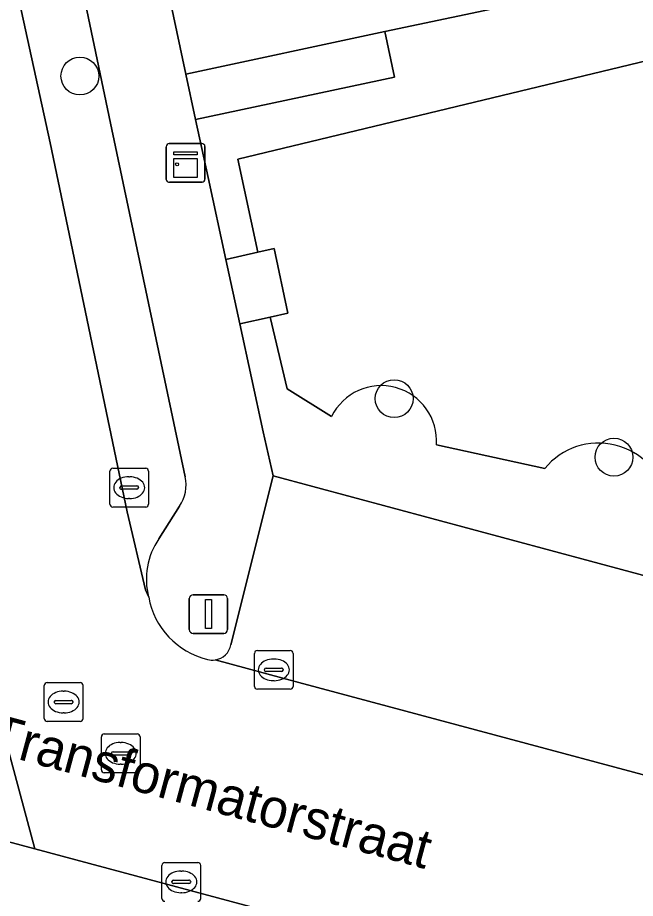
# Model space of a CAD drawing. Extents: x 162989 to 165008, y 383432 to 384338.
# Drawn here: x 163591.23 to 163607.2, y 383947.94 to 383970.69 of the extents above; entities that cross this region are included whole.
import ezdxf

# ---------------------------------------------------------------- set-up
doc = ezdxf.new("R2010")
doc.units = 0
for name, color, linetype in [('IMGEO_Boom', 7, 'Continuous'), ('IMGEO_Groenvoorziening', 7, 'Continuous'), ('IMGEO_Kast', 7, 'Continuous'), ('IMGEO_Kolk', 7, 'Continuous'), ('IMGEO_Lichtmast', 7, 'Continuous'), ('IMGEO_Openbare_ruimte_label', 7, 'Continuous'), ('IMGEO_Pand', 7, 'Continuous'), ('IMGEO_Parkeervlak_open', 7, 'Continuous'), ('IMGEO_Rijbaan_lokaal_open', 7, 'Continuous'), ('IMGEO_Rioolput', 7, 'Continuous'), ('IMGEO_Terreindeel_open', 7, 'Continuous'), ('IMGEO_Voetpad_open', 7, 'Continuous')]:
    doc.layers.add(name, color=color, linetype=linetype)

msp = doc.modelspace()

# ---------------------------------------------------------------- linework, layer by layer
at = {"layer": 'IMGEO_Boom'}
for centre in [(163592.845, 383969.176), (163600.967, 383960.844), (163606.648, 383959.331)]:
    msp.add_circle(centre, 0.489, dxfattribs=at)
at = {"layer": 'IMGEO_Groenvoorziening'}
for points in [[(163645.161, 383948.398), (163625.646, 383970.458), (163622.066, 383974.209), (163621.361, 383974.962), (163613.606, 383973.04), (163610.957, 383972.488), (163605.03, 383971.243), (163600.725, 383970.324), (163600.976, 383969.15), (163595.835, 383968.052), (163596.159, 383966.556), (163596.618, 383964.44), (163597.446, 383964.625), (163596.93, 383967.033), (163621.397, 383972.93), (163634.327, 383958.335), (163641.287, 383950.771), (163639.916, 383949.332), (163636.067, 383950.448)], [(163636.067, 383950.448), (163639.916, 383949.332), (163641.287, 383950.771), (163634.327, 383958.335), (163621.397, 383972.93), (163596.93, 383967.033), (163597.446, 383964.625), (163597.864, 383964.718), (163598.223, 383963.048), (163597.764, 383962.949), (163598.199, 383961.094), (163599.35, 383960.383)], [(163599.35, 383960.383), (163598.199, 383961.094), (163597.764, 383962.949), (163596.978, 383962.778), (163597.581, 383959.99), (163597.843, 383958.853), (163614.246, 383954.444), (163635.514, 383948.776), (163643.317, 383946.719), (163645.161, 383948.398)], [(163604.861, 383959.041), (163602.059, 383959.651)], [(163602.059, 383959.651), (163604.861, 383959.041)]]:
    msp.add_lwpolyline(points, dxfattribs=at)
for centre, radius, start, end in [((163600.632, 383959.749), 1.43, 356.062, 153.6963), ((163600.632, 383959.749), 1.43, 356.062, 153.6963), ((163606.248, 383957.904), 1.794, 11.5882, 140.6482), ((163606.248, 383957.904), 1.794, 11.5882, 140.6482)]:
    msp.add_arc(centre, radius, start, end, dxfattribs=at)
at = {"layer": 'IMGEO_Kast'}
for p, q in [((163595.078, 383966.507), (163595.078, 383967.348)), ((163595.078, 383967.348), (163595.078, 383966.507)), ((163595.153, 383967.432), (163595.994, 383967.432)), ((163595.994, 383967.432), (163595.153, 383967.432)), ((163596.078, 383967.357), (163596.078, 383966.516)), ((163596.078, 383966.516), (163596.078, 383967.357)), ((163596.003, 383966.432), (163595.162, 383966.432)), ((163595.162, 383966.432), (163596.003, 383966.432))]:
    msp.add_line(p, q, dxfattribs=at)
for points in [[(163595.273, 383967.222), (163595.873, 383967.222), (163595.873, 383967.137), (163595.273, 383967.137), (163595.273, 383967.222)], [(163595.273, 383967.047), (163595.873, 383967.047), (163595.873, 383966.558), (163595.273, 383966.558), (163595.273, 383967.047)]]:
    msp.add_lwpolyline(points, dxfattribs=at)
msp.add_circle((163595.357, 383966.896), 0.0377, dxfattribs=at)
for centre, start, end in [((163595.156, 383967.354), 92.4484, 184.2845), ((163595.156, 383967.354), 92.4484, 184.2845), ((163596, 383967.354), 2.4484, 94.2845), ((163596, 383967.354), 2.4484, 94.2845), ((163595.156, 383966.51), 182.4484, 274.2845), ((163595.156, 383966.51), 182.4484, 274.2845), ((163596, 383966.51), 272.4484, 4.2845), ((163596, 383966.51), 272.4484, 4.2845)]:
    msp.add_arc(centre, 0.0779, start, end, dxfattribs=at)
at = {"layer": 'IMGEO_Kolk'}
for p, q in [((163593.618, 383958.119), (163593.618, 383958.971)), ((163593.693, 383959.045), (163594.545, 383959.045)), ((163594.619, 383958.971), (163594.619, 383958.119)), ((163594.106, 383958.825), (163594.131, 383958.825)), ((163593.877, 383958.539), (163593.877, 383958.551)), ((163594.315, 383958.502), (163593.917, 383958.502)), ((163593.92, 383958.588), (163594.318, 383958.588)), ((163594.361, 383958.551), (163594.361, 383958.539)), ((163594.129, 383958.265), (163594.104, 383958.265)), ((163594.545, 383958.045), (163593.693, 383958.045)), ((163597.356, 383953.413), (163597.356, 383954.265)), ((163597.431, 383954.339), (163598.283, 383954.339)), ((163598.357, 383954.265), (163598.357, 383953.413)), ((163597.844, 383954.119), (163597.869, 383954.119)), ((163597.615, 383953.833), (163597.615, 383953.845)), ((163598.053, 383953.796), (163597.655, 383953.796)), ((163597.658, 383953.882), (163598.056, 383953.882)), ((163598.099, 383953.845), (163598.099, 383953.833)), ((163597.867, 383953.559), (163597.842, 383953.559)), ((163598.283, 383953.339), (163597.431, 383953.339)), ((163594.965, 383947.936), (163594.965, 383948.788)), ((163595.04, 383948.862), (163595.892, 383948.862)), ((163595.966, 383948.788), (163595.966, 383947.936)), ((163595.453, 383948.642), (163595.478, 383948.642)), ((163595.224, 383948.356), (163595.224, 383948.368)), ((163595.662, 383948.319), (163595.264, 383948.319)), ((163595.267, 383948.405), (163595.665, 383948.405)), ((163595.708, 383948.368), (163595.708, 383948.356)), ((163595.476, 383948.082), (163595.451, 383948.082))]:
    msp.add_line(p, q, dxfattribs=at)
for points in [[(163593.618, 383958.119), (163593.618, 383958.971)], [(163593.693, 383959.045), (163594.545, 383959.045)], [(163594.619, 383958.971), (163594.619, 383958.119)], [(163594.545, 383958.045), (163593.693, 383958.045)], [(163597.356, 383953.413), (163597.356, 383954.265)], [(163597.431, 383954.339), (163598.283, 383954.339)], [(163598.357, 383954.265), (163598.357, 383953.413)], [(163598.283, 383953.339), (163597.431, 383953.339)], [(163594.965, 383947.936), (163594.965, 383948.788)], [(163595.04, 383948.862), (163595.892, 383948.862)], [(163595.966, 383948.788), (163595.966, 383947.936)]]:
    msp.add_lwpolyline(points, dxfattribs=at)
for centre, radius, start, end in [((163593.695, 383958.969), 0.0765, 91.552, 178.448), ((163593.695, 383958.969), 0.0765, 91.552, 178.448), ((163594.543, 383958.969), 0.0765, 1.552, 88.448), ((163594.543, 383958.969), 0.0765, 1.552, 88.448), ((163593.917, 383958.548), 0.0403, 85.8775, 175.7526), ((163593.914, 383958.538), 0.0366, 178.938, 274.7102), ((163594.318, 383958.545), 0.043, 264.8664, 352.4533), ((163594.322, 383958.55), 0.0386, 1.7309, 96.639), ((163593.695, 383958.121), 0.0765, 181.552, 268.448), ((163593.695, 383958.121), 0.0765, 181.552, 268.448), ((163594.543, 383958.121), 0.0765, 271.552, 358.448), ((163594.543, 383958.121), 0.0765, 271.552, 358.448), ((163597.433, 383954.263), 0.0765, 91.552, 178.448), ((163597.433, 383954.263), 0.0765, 91.552, 178.448), ((163598.281, 383954.263), 0.0765, 1.552, 88.448), ((163598.281, 383954.263), 0.0765, 1.552, 88.448), ((163597.655, 383953.842), 0.0403, 85.8775, 175.7526), ((163597.652, 383953.832), 0.0366, 178.938, 274.7102), ((163598.056, 383953.839), 0.043, 264.8664, 352.4533), ((163598.06, 383953.844), 0.0386, 1.7309, 96.639), ((163597.433, 383953.415), 0.0765, 181.552, 268.448), ((163597.433, 383953.415), 0.0765, 181.552, 268.448), ((163598.281, 383953.415), 0.0765, 271.552, 358.448), ((163598.281, 383953.415), 0.0765, 271.552, 358.448), ((163595.042, 383948.786), 0.0765, 91.552, 178.448), ((163595.042, 383948.786), 0.0765, 91.552, 178.448), ((163595.89, 383948.786), 0.0765, 1.552, 88.448), ((163595.89, 383948.786), 0.0765, 1.552, 88.448), ((163595.264, 383948.365), 0.0403, 85.8775, 175.7526), ((163595.261, 383948.355), 0.0366, 178.938, 274.7102), ((163595.665, 383948.362), 0.043, 264.8664, 352.4533), ((163595.669, 383948.367), 0.0386, 1.7309, 96.639), ((163595.042, 383947.938), 0.0765, 181.552, 268.448), ((163595.042, 383947.938), 0.0765, 181.552, 268.448), ((163595.89, 383947.938), 0.0765, 271.552, 358.448), ((163595.89, 383947.938), 0.0765, 271.552, 358.448)]:
    msp.add_arc(centre, radius, start, end, dxfattribs=at)
for centre, major_axis, ratio, start_param, end_param in [((163594.105, 383958.545), (-0.387, 0.002), 0.722429, 4.712389, 7.853982), ((163594.13, 383958.545), (-0.39, 0.002), 0.717154, 1.570796, 4.712389), ((163597.843, 383953.839), (-0.387, 0.002), 0.722429, 4.712389, 7.853982), ((163597.868, 383953.839), (-0.39, 0.002), 0.717154, 1.570796, 4.712389), ((163595.452, 383948.362), (-0.387, 0.002), 0.722429, 4.712389, 7.853982), ((163595.477, 383948.362), (-0.39, 0.002), 0.717154, 1.570796, 4.712389)]:
    msp.add_ellipse(centre, major_axis=major_axis, ratio=ratio, start_param=start_param, end_param=end_param, dxfattribs=at)
at = {"layer": 'IMGEO_Lichtmast'}
for p, q in [((163595.773, 383955.779), (163596.563, 383955.779)), ((163596.563, 383955.779), (163595.773, 383955.779)), ((163595.673, 383954.879), (163595.673, 383955.679)), ((163595.673, 383955.679), (163595.673, 383954.879)), ((163596.663, 383955.679), (163596.663, 383954.879)), ((163596.663, 383954.879), (163596.663, 383955.679)), ((163596.563, 383954.779), (163595.773, 383954.779)), ((163595.773, 383954.779), (163596.563, 383954.779))]:
    msp.add_line(p, q, dxfattribs=at)
msp.add_lwpolyline([(163596.093, 383955.654), (163596.243, 383955.654), (163596.243, 383954.904), (163596.093, 383954.904), (163596.093, 383955.654)], dxfattribs=at)
for centre, start, end in [((163595.773, 383955.679), 90, 180), ((163595.773, 383955.679), 90, 180), ((163596.563, 383955.679), 0, 90), ((163596.563, 383955.679), 360, 90), ((163595.773, 383954.879), 180, 270), ((163595.773, 383954.879), 180, 270), ((163596.563, 383954.879), 270, 0), ((163596.563, 383954.879), 270, 0)]:
    msp.add_arc(centre, 0.1, start, end, dxfattribs=at)
at = {"layer": 'IMGEO_Pand'}
msp.add_lwpolyline([(163594.418, 383974.701), (163595.581, 383969.225), (163600.725, 383970.324), (163605.03, 383971.243), (163604.966, 383971.547), (163604.751, 383971.502), (163603.653, 383976.675)], close=True, dxfattribs=at)
at = {"layer": 'IMGEO_Parkeervlak_open'}
for points in [[(163586.603, 383993.258), (163586.661, 383992.819), (163586.73, 383992.527), (163590.906, 383972.826), (163592.074, 383967.448), (163594.067, 383957.923), (163594.543, 383955.908), (163594.623, 383955.718)], [(163595.566, 383958.824), (163593.64, 383967.963), (163591.271, 383979.268)], [(163597.843, 383958.853), (163596.748, 383954.489)], [(163644.299, 383943.287), (163645.105, 383946.248), (163644.933, 383946.293), (163643.317, 383946.719), (163635.514, 383948.776), (163614.246, 383954.444), (163597.843, 383958.853)], [(163594.884, 383957.224), (163595.418, 383958.065)], [(163596.338, 383954.095), (163598.503, 383953.515), (163613.036, 383949.618), (163631.635, 383944.624), (163644.707, 383941.132), (163645.699, 383940.867)]]:
    msp.add_lwpolyline(points, dxfattribs=at)
for centre, radius, start, end in [((163594.614, 383958.616), 0.974, 325.5894, 12.3429), ((163596.404, 383956.185), 1.842, 145.6505, 194.6853), ((163596.276, 383954.569), 0.478, 277.3912, 350.3286)]:
    msp.add_arc(centre, radius, start, end, dxfattribs=at)
at = {"layer": 'IMGEO_Rijbaan_lokaal_open'}
for points in [[(163594.623, 383955.718), (163594.543, 383955.908), (163594.067, 383957.923), (163592.074, 383967.448), (163590.906, 383972.826), (163586.73, 383992.527), (163586.661, 383992.819), (163586.603, 383993.258), (163582.284, 383991.686), (163583.125, 383987.664), (163587.549, 383967.036), (163590.09, 383955.124), (163591.682, 383949.215), (163602.315, 383946.365), (163616.922, 383942.467), (163650.042, 383933.629)], [(163572.767, 383954.309), (163577.576, 383952.996), (163591.682, 383949.215), (163590.09, 383955.124)], [(163651.448, 383939.329), (163650.575, 383939.559), (163649.686, 383939.794), (163648.69, 383940.057), (163645.699, 383940.867), (163644.707, 383941.132), (163631.635, 383944.624), (163613.036, 383949.618), (163598.503, 383953.515), (163596.338, 383954.095)]]:
    msp.add_lwpolyline(points, dxfattribs=at)
for centre, radius, start, end in [((163596.609, 383956.073), 2.018, 190.1335, 256.6059), ((163596.275, 383954.554), 0.463, 253.3753, 277.872)]:
    msp.add_arc(centre, radius, start, end, dxfattribs=at)
at = {"layer": 'IMGEO_Rioolput'}
for p, q in [((163591.999, 383953.508), (163592.851, 383953.508)), ((163591.924, 383952.582), (163591.924, 383953.434)), ((163592.412, 383953.288), (163592.437, 383953.288)), ((163592.925, 383953.434), (163592.925, 383952.582)), ((163592.183, 383953.002), (163592.183, 383953.014)), ((163592.226, 383953.051), (163592.624, 383953.051)), ((163592.667, 383953.014), (163592.667, 383953.002)), ((163592.621, 383952.965), (163592.223, 383952.965)), ((163592.435, 383952.728), (163592.41, 383952.728)), ((163592.851, 383952.508), (163591.999, 383952.508)), ((163593.399, 383951.256), (163593.399, 383952.108)), ((163593.474, 383952.182), (163594.326, 383952.182)), ((163594.4, 383952.108), (163594.4, 383951.256)), ((163593.887, 383951.962), (163593.912, 383951.962)), ((163593.658, 383951.676), (163593.658, 383951.688)), ((163594.096, 383951.639), (163593.698, 383951.639)), ((163593.701, 383951.725), (163594.099, 383951.725)), ((163594.142, 383951.688), (163594.142, 383951.676)), ((163594.326, 383951.182), (163593.474, 383951.182)), ((163593.91, 383951.402), (163593.885, 383951.402))]:
    msp.add_line(p, q, dxfattribs=at)
for points in [[(163591.999, 383953.508), (163592.851, 383953.508)], [(163591.924, 383952.582), (163591.924, 383953.434)], [(163592.925, 383953.434), (163592.925, 383952.582)], [(163592.851, 383952.508), (163591.999, 383952.508)], [(163593.399, 383951.256), (163593.399, 383952.108)], [(163593.474, 383952.182), (163594.326, 383952.182)], [(163594.4, 383952.108), (163594.4, 383951.256)], [(163594.326, 383951.182), (163593.474, 383951.182)]]:
    msp.add_lwpolyline(points, dxfattribs=at)
for centre, radius, start, end in [((163592.001, 383953.432), 0.0765, 91.552, 178.448), ((163592.001, 383953.432), 0.0765, 91.552, 178.448), ((163592.849, 383953.432), 0.0765, 1.552, 88.448), ((163592.849, 383953.432), 0.0765, 1.552, 88.448), ((163592.223, 383953.011), 0.0403, 85.8775, 175.7526), ((163592.22, 383953.001), 0.0366, 178.938, 274.7102), ((163592.624, 383953.008), 0.043, 264.8664, 352.4533), ((163592.628, 383953.013), 0.0386, 1.7309, 96.639), ((163592.001, 383952.584), 0.0765, 181.552, 268.448), ((163592.001, 383952.584), 0.0765, 181.552, 268.448), ((163592.849, 383952.584), 0.0765, 271.552, 358.448), ((163592.849, 383952.584), 0.0765, 271.552, 358.448), ((163593.476, 383952.106), 0.0765, 91.552, 178.448), ((163593.476, 383952.106), 0.0765, 91.552, 178.448), ((163594.324, 383952.106), 0.0765, 1.552, 88.448), ((163594.324, 383952.106), 0.0765, 1.552, 88.448), ((163593.698, 383951.685), 0.0403, 85.8775, 175.7526), ((163593.695, 383951.675), 0.0366, 178.938, 274.7102), ((163594.099, 383951.682), 0.043, 264.8664, 352.4533), ((163594.103, 383951.687), 0.0386, 1.7309, 96.639), ((163593.476, 383951.258), 0.0765, 181.552, 268.448), ((163593.476, 383951.258), 0.0765, 181.552, 268.448), ((163594.324, 383951.258), 0.0765, 271.552, 358.448), ((163594.324, 383951.258), 0.0765, 271.552, 358.448)]:
    msp.add_arc(centre, radius, start, end, dxfattribs=at)
for centre, major_axis, ratio, start_param, end_param in [((163592.411, 383953.008), (-0.387, 0.002), 0.722429, 4.712389, 7.853982), ((163592.436, 383953.008), (-0.39, 0.002), 0.717154, 1.570796, 4.712389), ((163593.886, 383951.682), (-0.387, 0.002), 0.722429, 4.712389, 7.853982), ((163593.911, 383951.682), (-0.39, 0.002), 0.717154, 1.570796, 4.712389)]:
    msp.add_ellipse(centre, major_axis=major_axis, ratio=ratio, start_param=start_param, end_param=end_param, dxfattribs=at)
at = {"layer": 'IMGEO_Terreindeel_open'}
msp.add_lwpolyline([(163597.764, 383962.949), (163598.223, 383963.048), (163597.864, 383964.718), (163597.446, 383964.625), (163596.618, 383964.44), (163596.978, 383962.778)], close=True, dxfattribs=at)
at = {"layer": 'IMGEO_Voetpad_open'}
for points in [[(163588.784, 383991.063), (163591.271, 383979.268), (163593.64, 383967.963), (163595.566, 383958.824)], [(163596.748, 383954.489), (163597.843, 383958.853), (163597.581, 383959.99), (163596.978, 383962.778), (163596.618, 383964.44), (163596.159, 383966.556), (163595.835, 383968.052), (163595.581, 383969.225), (163594.418, 383974.701)], [(163595.418, 383958.065), (163594.884, 383957.224)], [(163591.682, 383949.215), (163577.576, 383952.996), (163572.767, 383954.309)], [(163650.042, 383933.629), (163616.922, 383942.467), (163602.315, 383946.365), (163591.682, 383949.215)]]:
    msp.add_lwpolyline(points, dxfattribs=at)
msp.add_lwpolyline([(163600.976, 383969.15), (163600.725, 383970.324), (163595.581, 383969.225), (163595.835, 383968.052)], close=True, dxfattribs=at)
for centre, radius, start, end in [((163594.614, 383958.616), 0.974, 325.5894, 12.3429), ((163596.404, 383956.185), 1.842, 145.6505, 194.6853), ((163596.609, 383956.073), 2.018, 190.1335, 256.6059), ((163596.276, 383954.569), 0.478, 277.3912, 350.3286), ((163596.275, 383954.554), 0.463, 253.3753, 277.872)]:
    msp.add_arc(centre, radius, start, end, dxfattribs=at)

# ---------------------------------------------------------------- texts
at = {"layer": 'IMGEO_Openbare_ruimte_label'}
msp.add_text('Transformatorstraat', height=1, rotation=344.9209, dxfattribs=at).set_placement((163590.427, 383951.751))

doc.saveas('drawing.dxf')
